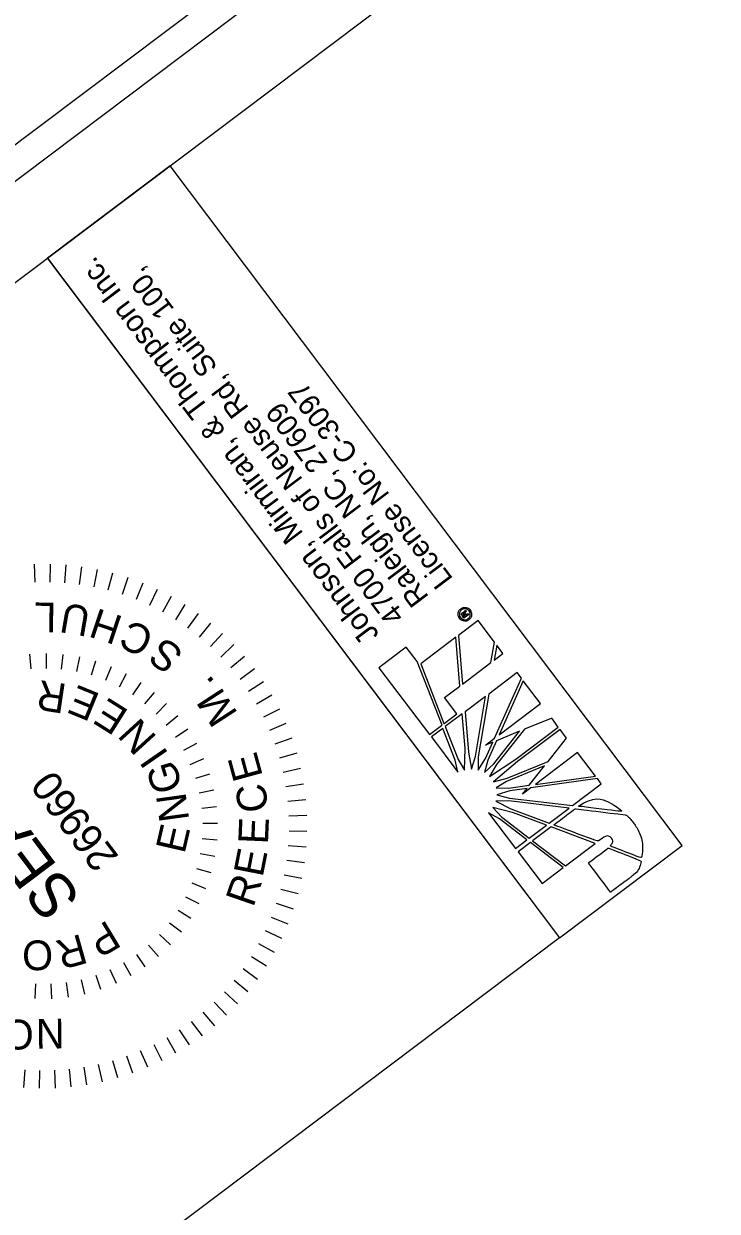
# Model space of a CAD drawing. Extents: x 1262861 to 1264804, y 775326 to 777329.
# Drawn here: x 1263050.9 to 1263158, y 776605.9 to 776789.4 of the extents above; entities that cross this region are included whole.
import ezdxf

# ---------------------------------------------------------------- set-up
doc = ezdxf.new("R2010")
doc.units = 0
for name, color, linetype in [('Default', 7, 'Continuous'), ('Sheet Data Field CELL', 7, 'Continuous'), ('Sheet Plan CELL', 7, 'Continuous'), ('Sheet Plot Border Inside CELL', 7, 'Continuous'), ('Sheet Plot Border Outside CELL', 7, 'Continuous'), ('Sheet Typical CELL', 7, 'Continuous')]:
    doc.layers.add(name, color=color, linetype=linetype)

msp = doc.modelspace()

# ---------------------------------------------------------------- linework, layer by layer
at = {"layer": 'Default'}
for p, q in [((1263052.5, 776705.87), (1263052.61, 776703.11)), ((1263054.94, 776705.89), (1263054.89, 776703.13)), ((1263057.39, 776705.77), (1263057.17, 776703.02)), ((1263059.82, 776705.5), (1263059.43, 776702.77)), ((1263062.23, 776705.08), (1263061.68, 776702.38)), ((1263064.61, 776704.52), (1263063.89, 776701.86)), ((1263066.95, 776703.82), (1263066.08, 776701.2)), ((1263069.25, 776702.98), (1263068.22, 776700.41)), ((1263071.49, 776701.99), (1263070.3, 776699.5)), ((1263073.66, 776700.88), (1263072.33, 776698.46)), ((1263075.77, 776699.64), (1263074.3, 776697.3)), ((1263077.8, 776698.27), (1263076.18, 776696.03)), ((1263079.74, 776696.78), (1263077.99, 776694.64)), ((1263081.59, 776695.18), (1263079.71, 776693.15)), ((1263083.33, 776693.46), (1263081.34, 776691.55)), ((1263051.77, 776691.99), (1263051.98, 776689.7)), ((1263054.35, 776692.1), (1263054.33, 776689.8)), ((1263056.92, 776691.95), (1263056.68, 776689.67)), ((1263059.47, 776691.56), (1263059.01, 776689.3)), ((1263084.97, 776691.65), (1263082.87, 776689.86)), ((1263061.97, 776690.92), (1263061.29, 776688.72)), ((1263064.39, 776690.05), (1263063.51, 776687.92)), ((1263086.5, 776689.74), (1263084.29, 776688.08)), ((1263066.72, 776688.94), (1263065.64, 776686.91)), ((1263068.94, 776687.62), (1263067.66, 776685.7)), ((1263087.91, 776687.74), (1263085.61, 776686.22)), ((1263071.01, 776686.08), (1263069.55, 776684.3)), ((1263089.2, 776685.66), (1263086.81, 776684.28)), ((1263072.93, 776684.36), (1263071.31, 776682.73)), ((1263074.67, 776682.46), (1263072.9, 776680.99)), ((1263090.36, 776683.51), (1263087.89, 776682.28)), ((1263076.22, 776680.4), (1263074.32, 776679.1)), ((1263091.38, 776681.29), (1263088.85, 776680.21)), ((1263092.28, 776679.01), (1263089.67, 776678.08)), ((1263077.56, 776678.2), (1263075.54, 776677.09)), ((1263093.03, 776676.69), (1263090.37, 776675.92)), ((1263076.57, 776674.96), (1263078.69, 776675.86)), ((1263079.58, 776673.46), (1263077.38, 776672.77)), ((1263093.63, 776674.32), (1263090.94, 776673.71)), ((1263080.24, 776670.96), (1263077.98, 776670.49)), ((1263094.1, 776671.92), (1263091.38, 776671.47)), ((1263094.42, 776669.49), (1263091.67, 776669.21)), ((1263080.65, 776668.42), (1263078.36, 776668.16)), ((1263080.82, 776665.85), (1263078.52, 776665.81)), ((1263094.59, 776667.05), (1263091.84, 776666.94)), ((1263094.62, 776664.61), (1263091.86, 776664.66)), ((1263080.74, 776663.27), (1263078.44, 776663.45)), ((1263094.49, 776662.16), (1263091.74, 776662.38)), ((1263080.4, 776660.71), (1263078.14, 776661.12)), ((1263094.22, 776659.73), (1263091.49, 776660.12)), ((1263079.83, 776658.2), (1263077.61, 776658.82)), ((1263079.01, 776655.75), (1263076.87, 776656.59)), ((1263093.81, 776657.32), (1263091.11, 776657.87)), ((1263077.96, 776653.4), (1263075.91, 776654.43)), ((1263093.25, 776654.94), (1263090.58, 776655.65)), ((1263092.54, 776652.6), (1263089.93, 776653.47)), ((1263076.7, 776651.16), (1263074.75, 776652.38)), ((1263091.7, 776650.3), (1263089.14, 776651.33)), ((1263075.22, 776649.04), (1263073.4, 776650.45)), ((1263090.72, 776648.06), (1263088.23, 776649.24)), ((1263073.53, 776647.09), (1263071.86, 776648.66)), ((1263089.6, 776645.89), (1263087.19, 776647.22)), ((1263069.65, 776643.7), (1263068.32, 776645.57)), ((1263071.68, 776645.3), (1263070.17, 776647.03)), ((1263088.36, 776643.78), (1263086.03, 776645.25)), ((1263067.48, 776642.3), (1263066.33, 776644.29)), ((1263060.32, 776639.45), (1263059.79, 776641.69)), ((1263062.8, 776640.17), (1263062.05, 776642.35)), ((1263065.19, 776641.12), (1263064.24, 776643.22)), ((1263085.5, 776639.81), (1263083.37, 776641.56)), ((1263087, 776641.75), (1263084.75, 776643.37)), ((1263052.64, 776638.77), (1263052.77, 776641.06)), ((1263055.22, 776638.75), (1263055.13, 776641.05)), ((1263057.78, 776638.98), (1263057.47, 776641.26)), ((1263083.9, 776637.96), (1263081.87, 776639.83)), ((1263082.19, 776636.22), (1263080.28, 776638.21)), ((1263080.38, 776634.58), (1263078.59, 776636.68)), ((1263078.47, 776633.05), (1263076.81, 776635.25)), ((1263074.39, 776630.35), (1263073.01, 776632.74)), ((1263076.47, 776631.64), (1263074.94, 776633.94)), ((1263070.02, 776628.17), (1263068.93, 776630.7)), ((1263072.24, 776629.19), (1263071, 776631.66)), ((1263065.41, 776626.52), (1263064.64, 776629.18)), ((1263067.74, 776627.27), (1263066.81, 776629.88)), ((1263050.89, 776625.05), (1263051.11, 776627.8)), ((1263053.33, 776624.93), (1263053.38, 776627.69)), ((1263055.77, 776624.96), (1263055.66, 776627.71)), ((1263058.21, 776625.13), (1263057.94, 776627.87)), ((1263060.64, 776625.45), (1263060.2, 776628.17)), ((1263063.04, 776625.92), (1263062.43, 776628.61))]:
    msp.add_line(p, q, dxfattribs=at)
at = {"layer": 'Sheet Data Field CELL'}
for p, q in [((1263119.67, 776698.65), (1263119.66, 776698.66)), ((1263119.67, 776698.65), (1263119.83, 776698.77)), ((1263119.83, 776698.77), (1263119.67, 776698.65)), ((1263119.83, 776698.78), (1263119.83, 776698.77)), ((1263121.05, 776697.18), (1263118, 776694.88)), ((1263118.18, 776697.53), (1263118.34, 776697.65)), ((1263118.34, 776697.65), (1263118.18, 776697.53)), ((1263118.62, 776697.86), (1263118.59, 776697.91)), ((1263118.62, 776697.86), (1263118.77, 776697.97)), ((1263118.77, 776697.97), (1263118.62, 776697.86)), ((1263118.86, 776697.56), (1263118.62, 776697.86)), ((1263118.75, 776697.99), (1263118.77, 776697.97)), ((1263118.77, 776697.97), (1263118.87, 776697.83)), ((1263119.61, 776698.12), (1263118.86, 776697.56)), ((1263118.87, 776697.83), (1263119.05, 776697.97)), ((1263118.95, 776698.1), (1263118.94, 776698.11)), ((1263118.95, 776698.1), (1263119.08, 776698.21)), ((1263119.08, 776698.21), (1263118.95, 776698.1)), ((1263119.05, 776697.97), (1263118.95, 776698.1)), ((1263119.08, 776698.21), (1263119.18, 776698.07)), ((1263119.08, 776698.21), (1263119.08, 776698.21)), ((1263119.18, 776698.07), (1263119.48, 776698.29)), ((1263119.48, 776698.29), (1263119.61, 776698.12)), ((1263123.56, 776693.85), (1263121.05, 776697.18)), ((1263118, 776694.88), (1263118.64, 776687.38)), ((1263109.96, 776693.08), (1263105.74, 776689.88)), ((1263111.62, 776690.88), (1263109.96, 776693.08)), ((1263117.62, 776694.59), (1263112.2, 776690.5)), ((1263118.23, 776687.07), (1263117.62, 776694.59)), ((1263123.03, 776690.69), (1263123.56, 776693.85)), ((1263123.93, 776693.36), (1263123.51, 776691.05)), ((1263124.89, 776692.09), (1263123.93, 776693.36)), ((1263123.51, 776691.05), (1263124.89, 776692.09)), ((1263105.74, 776689.88), (1263113.53, 776679.56)), ((1263115.48, 776681.04), (1263111.62, 776690.88)), ((1263112.2, 776690.5), (1263115.77, 776681.26)), ((1263118.64, 776687.38), (1263123.03, 776690.69)), ((1263127.1, 776689.16), (1263122.69, 776685.83)), ((1263123.6, 776679), (1263127.75, 776688.29)), ((1263128.03, 776687.87), (1263124.3, 776679.53)), ((1263127.75, 776688.29), (1263127.1, 776689.16)), ((1263130.69, 776684.35), (1263128.03, 776687.87)), ((1263115.88, 776685.29), (1263118.23, 776687.07)), ((1263122.69, 776685.83), (1263121.07, 776676.15)), ((1263117.78, 776682.77), (1263115.88, 776685.29)), ((1263122.18, 776685.45), (1263119.04, 776683.08)), ((1263120.66, 776676.19), (1263122.18, 776685.45)), ((1263124.3, 776679.53), (1263130.69, 776684.35)), ((1263115.8, 776681.28), (1263117.78, 776682.77)), ((1263118.6, 776682.75), (1263115.98, 776680.81)), ((1263119.07, 776677.4), (1263118.6, 776682.75)), ((1263119.04, 776683.08), (1263119.54, 776676.83)), ((1263132.41, 776682.08), (1263128.23, 776680.41)), ((1263133.43, 776680.72), (1263132.41, 776682.08)), ((1263113.53, 776679.56), (1263115.42, 776680.99)), ((1263115.6, 776680.53), (1263113.84, 776679.2)), ((1263115.42, 776680.99), (1263115.48, 776681.04)), ((1263117.53, 776675.6), (1263115.6, 776680.53)), ((1263115.77, 776681.26), (1263115.8, 776681.28)), ((1263115.98, 776680.81), (1263117.99, 776675.74)), ((1263123.46, 776675.07), (1263127.46, 776680.09)), ((1263127.46, 776680.09), (1263123.89, 776678.62)), ((1263128.23, 776680.41), (1263123.91, 776674.94)), ((1263126.89, 776675.77), (1263133.43, 776680.72)), ((1263133.7, 776680.37), (1263127.15, 776675.43)), ((1263134.71, 776679.02), (1263133.7, 776680.37)), ((1263113.84, 776679.2), (1263117.92, 776673.74)), ((1263122.17, 776677.92), (1263123.6, 776679)), ((1263122.17, 776675.88), (1263123.33, 776678.4)), ((1263123.33, 776678.4), (1263122.17, 776677.92)), ((1263123.89, 776678.62), (1263122.55, 776675.61)), ((1263131.87, 776675.43), (1263134.71, 776679.02)), ((1263118.94, 776674.07), (1263119.07, 776677.4)), ((1263119.54, 776676.83), (1263120.02, 776674.22)), ((1263136.41, 776676.82), (1263129.89, 776671.85)), ((1263139.17, 776673.16), (1263136.41, 776676.82)), ((1263117.92, 776673.74), (1263117.53, 776675.6)), ((1263117.99, 776675.74), (1263118.94, 776674.07)), ((1263120.02, 776674.22), (1263120.66, 776676.19)), ((1263121.07, 776676.15), (1263121.05, 776674.09)), ((1263121.05, 776674.09), (1263122.17, 776675.88)), ((1263122.55, 776675.61), (1263122.01, 776673.72)), ((1263122.01, 776673.72), (1263123.46, 776675.07)), ((1263122.83, 776673.1), (1263126.89, 776675.77)), ((1263123.91, 776674.94), (1263122.83, 776673.1)), ((1263127.15, 776675.43), (1263123.44, 776672.29)), ((1263131.31, 776674.75), (1263125.45, 776672.32)), ((1263125.52, 776672.81), (1263131.87, 776675.43)), ((1263128.95, 776671.74), (1263131.31, 776674.75)), ((1263123.44, 776672.29), (1263125.52, 776672.81)), ((1263139.46, 776672.78), (1263129.18, 776671.32)), ((1263129.89, 776671.85), (1263139.17, 776673.16)), ((1263140.07, 776671.97), (1263139.46, 776672.78)), ((1263125.45, 776672.32), (1263123.83, 776671.32)), ((1263123.83, 776671.32), (1263125.81, 776671.29)), ((1263125.81, 776671.29), (1263128.95, 776671.74)), ((1263128.6, 776671.25), (1263125.95, 776670.87)), ((1263129.18, 776671.32), (1263127.89, 776670.34)), ((1263127.89, 776670.34), (1263128.6, 776671.25)), ((1263135.62, 776668.6), (1263140.07, 776671.97)), ((1263125.8, 776669.32), (1263123.76, 776669.27)), ((1263123.76, 776669.27), (1263126.12, 776668.11)), ((1263125.95, 776670.87), (1263123.92, 776670.28)), ((1263123.92, 776670.28), (1263125.91, 776669.74)), ((1263135.1, 776668.21), (1263125.8, 776669.32)), ((1263125.91, 776669.74), (1263135.62, 776668.6)), ((1263124.33, 776666.55), (1263122.64, 776667.48)), ((1263122.64, 776667.48), (1263126.81, 776661.96)), ((1263126.49, 776667.5), (1263123.3, 776668.29)), ((1263123.3, 776668.29), (1263124.71, 776666.83)), ((1263126.12, 776668.11), (1263132.04, 776665.9)), ((1263131.61, 776665.58), (1263126.49, 776667.5)), ((1263132.04, 776665.9), (1263135.1, 776668.21)), ((1263128.57, 776663.29), (1263124.33, 776666.55)), ((1263124.71, 776666.83), (1263128.95, 776663.57)), ((1263128.95, 776663.57), (1263131.61, 776665.58)), ((1263132.32, 776665.31), (1263129.47, 776663.17)), ((1263139.13, 776662.75), (1263132.32, 776665.31)), ((1263126.81, 776661.96), (1263128.57, 776663.29)), ((1263129.12, 776662.9), (1263127.22, 776661.47)), ((1263134.18, 776659.02), (1263129.12, 776662.9)), ((1263129.47, 776663.17), (1263134.56, 776659.3)), ((1263134.56, 776659.3), (1263139.13, 776662.75)), ((1263127.22, 776661.47), (1263130.93, 776656.56)), ((1263130.93, 776656.56), (1263134.18, 776659.02))]:
    msp.add_line(p, q, dxfattribs=at)
msp.add_lwpolyline([(1263152.55, 776662.43), (1263073.48, 776767.42), (1263054.53, 776753.15), (1263133.61, 776648.16)], close=True, dxfattribs=at)
for points in [[(1263118.95, 776698.62), (1263118.99, 776698.65), (1263119.01, 776698.68), (1263119.04, 776698.7), (1263119.11, 776698.78), (1263119.23, 776698.63)], [(1263118.64, 776687.38), (1263123.03, 776690.69), (1263123.56, 776693.85), (1263121.05, 776697.18), (1263118, 776694.88), (1263118.64, 776687.38), (1263118.64, 776687.38)], [(1263105.74, 776689.88), (1263113.53, 776679.56), (1263115.42, 776680.99), (1263115.48, 776681.04), (1263111.62, 776690.88), (1263109.96, 776693.08), (1263105.74, 776689.88)], [(1263115.77, 776681.26), (1263115.8, 776681.28), (1263117.78, 776682.77), (1263115.88, 776685.29), (1263118.23, 776687.07), (1263117.62, 776694.59), (1263112.2, 776690.5), (1263115.77, 776681.26)], [(1263124.89, 776692.09), (1263124.89, 776692.09), (1263123.93, 776693.36), (1263123.51, 776691.05), (1263124.89, 776692.09)], [(1263121.05, 776674.09), (1263122.17, 776675.88), (1263123.33, 776678.4), (1263122.17, 776677.92), (1263123.6, 776679), (1263127.75, 776688.29), (1263127.1, 776689.16), (1263122.69, 776685.83), (1263121.07, 776676.15), (1263121.05, 776674.09)], [(1263130.69, 776684.35), (1263128.03, 776687.87), (1263124.3, 776679.53), (1263130.69, 776684.35)], [(1263120.02, 776674.22), (1263120.66, 776676.19), (1263122.18, 776685.45), (1263119.04, 776683.08), (1263119.54, 776676.83), (1263120.02, 776674.22)], [(1263118.94, 776674.07), (1263119.07, 776677.4), (1263118.6, 776682.75), (1263115.98, 776680.81), (1263117.99, 776675.74), (1263118.94, 776674.07)], [(1263122.83, 776673.1), (1263126.89, 776675.77), (1263133.43, 776680.72), (1263132.41, 776682.08), (1263128.23, 776680.41), (1263123.91, 776674.94), (1263122.83, 776673.1)], [(1263117.53, 776675.6), (1263115.6, 776680.53), (1263113.84, 776679.2), (1263117.92, 776673.74), (1263117.53, 776675.6)], [(1263122.01, 776673.72), (1263123.46, 776675.07), (1263127.46, 776680.09), (1263123.89, 776678.62), (1263122.55, 776675.61), (1263122.01, 776673.72)], [(1263125.52, 776672.81), (1263131.87, 776675.43), (1263134.71, 776679.02), (1263133.7, 776680.37), (1263127.15, 776675.43), (1263123.44, 776672.29), (1263125.52, 776672.81)], [(1263139.17, 776673.16), (1263136.41, 776676.82), (1263129.89, 776671.85), (1263139.17, 776673.16)], [(1263123.83, 776671.32), (1263125.81, 776671.29), (1263128.95, 776671.74), (1263131.31, 776674.75), (1263125.45, 776672.32), (1263123.83, 776671.32)], [(1263123.92, 776670.28), (1263125.91, 776669.74), (1263135.62, 776668.6), (1263140.07, 776671.97), (1263139.46, 776672.78), (1263129.18, 776671.32), (1263127.89, 776670.34), (1263128.6, 776671.25), (1263125.95, 776670.87), (1263123.92, 776670.28)], [(1263132.04, 776665.9), (1263135.1, 776668.21), (1263125.8, 776669.32), (1263123.76, 776669.27), (1263126.12, 776668.11), (1263132.04, 776665.9)], [(1263124.33, 776666.55), (1263122.64, 776667.48), (1263126.81, 776661.96), (1263128.57, 776663.29), (1263124.33, 776666.55)], [(1263128.95, 776663.57), (1263131.61, 776665.58), (1263126.49, 776667.5), (1263123.3, 776668.29), (1263124.71, 776666.83), (1263128.95, 776663.57)], [(1263139.13, 776662.75), (1263132.32, 776665.31), (1263129.47, 776663.17), (1263134.56, 776659.3), (1263139.13, 776662.75)], [(1263134.18, 776659.02), (1263129.12, 776662.9), (1263127.22, 776661.47), (1263130.93, 776656.56), (1263134.18, 776659.02)]]:
    msp.add_lwpolyline(points, dxfattribs=at)
for points, degree in [([(1263118.18, 776697.53), (1263118.01, 776697.76), (1263117.94, 776698.02), (1263117.97, 776698.3), (1263118, 776698.58), (1263118.13, 776698.81), (1263118.37, 776698.99)], 3), ([(1263119.66, 776698.66), (1263119.52, 776698.84), (1263119.34, 776698.95), (1263119.12, 776698.98), (1263118.89, 776699.02), (1263118.67, 776698.96), (1263118.49, 776698.82), (1263118.31, 776698.68), (1263118.19, 776698.49), (1263118.16, 776698.26), (1263118.14, 776698.04), (1263118.19, 776697.84), (1263118.34, 776697.65)], 3), ([(1263119.83, 776698.77), (1263120, 776698.55), (1263120.07, 776698.29), (1263120.03, 776698), (1263120, 776697.72), (1263119.86, 776697.49), (1263119.63, 776697.31), (1263119.4, 776697.14), (1263119.14, 776697.07), (1263118.86, 776697.12), (1263118.58, 776697.17), (1263118.36, 776697.3), (1263118.18, 776697.53)], 3), ([(1263118.34, 776697.65), (1263118.48, 776697.46), (1263118.66, 776697.35), (1263118.88, 776697.31), (1263119.11, 776697.28), (1263119.32, 776697.34), (1263119.5, 776697.48), (1263119.69, 776697.62), (1263119.8, 776697.81), (1263119.83, 776698.04), (1263119.86, 776698.26), (1263119.81, 776698.47), (1263119.67, 776698.65)], 3), ([(1263118.37, 776698.99), (1263118.6, 776699.16), (1263118.86, 776699.23), (1263119.14, 776699.19), (1263119.42, 776699.15), (1263119.65, 776699.01), (1263119.83, 776698.78)], 3), ([(1263118.59, 776697.91), (1263118.44, 776698.1), (1263118.45, 776698.25), (1263118.6, 776698.37), (1263118.67, 776698.42), (1263118.74, 776698.43), (1263118.83, 776698.4)], 3), ([(1263118.83, 776698.4), (1263118.82, 776698.47), (1263118.86, 776698.54), (1263118.95, 776698.62)], 2), ([(1263119.23, 776698.63), (1263119.2, 776698.58), (1263119.17, 776698.53), (1263119.12, 776698.49), (1263119.05, 776698.44), (1263119.01, 776698.4), (1263119.01, 776698.36)], 3), ([(1263118.94, 776698.11), (1263118.86, 776698.22), (1263118.78, 776698.25), (1263118.72, 776698.2), (1263118.67, 776698.16), (1263118.68, 776698.09), (1263118.75, 776697.99)], 3), ([(1263119.01, 776698.36), (1263119.01, 776698.33), (1263119.03, 776698.28), (1263119.08, 776698.21)], 2), ([(1263136.55, 776668.5), (1263136.55, 776668.5), (1263143.38, 776667.66), (1263143.38, 776667.66), (1263141.5, 776669.18), (1263138.86, 776670.11), (1263136.55, 776668.5)], 3), ([(1263141.65, 776663.54), (1263141.87, 776663.25), (1263141.9, 776662.88), (1263141.43, 776662.36), (1263141.43, 776662.36), (1263146.27, 776660.48), (1263146.27, 776660.48), (1263146.6, 776662.43), (1263145.97, 776664.68), (1263144.86, 776666.15), (1263144.57, 776666.53), (1263144.32, 776666.79), (1263143.93, 776667.14), (1263143.93, 776667.14), (1263136.03, 776668.11), (1263136.03, 776668.11), (1263136.03, 776668.11), (1263132.72, 776665.62), (1263132.72, 776665.62), (1263132.72, 776665.62), (1263139.55, 776663.06), (1263139.55, 776663.06), (1263140.79, 776664), (1263141.34, 776663.95), (1263141.65, 776663.54)], 3), ([(1263141.65, 776663.54), (1263141.87, 776663.25), (1263141.9, 776662.88), (1263141.43, 776662.36), (1263141.43, 776662.36), (1263146.27, 776660.48), (1263146.27, 776660.48), (1263146.6, 776662.43), (1263145.97, 776664.68), (1263144.86, 776666.15), (1263144.57, 776666.53), (1263144.32, 776666.79), (1263143.93, 776667.14), (1263143.93, 776667.14), (1263136.03, 776668.11), (1263136.03, 776668.11), (1263136.03, 776668.11), (1263132.72, 776665.62), (1263132.72, 776665.62), (1263132.72, 776665.62), (1263139.55, 776663.06), (1263139.55, 776663.06), (1263140.79, 776664), (1263141.34, 776663.95), (1263141.65, 776663.54)], 3), ([(1263138.09, 776659.75), (1263138.09, 776659.75), (1263141.52, 776655.21), (1263141.52, 776655.21), (1263141.52, 776655.21), (1263144.36, 776657.35), (1263144.36, 776657.35), (1263144.36, 776657.35), (1263144.66, 776657.58), (1263144.66, 776657.58), (1263145.55, 776658.25), (1263146.04, 776659.08), (1263146.24, 776660.04), (1263146.24, 776660.04), (1263141.15, 776662.06), (1263141.1, 776662.02), (1263141.1, 776662.02), (1263138.09, 776659.75), (1263138.09, 776659.75)], 3)]:
    msp.add_open_spline(points, degree=degree, dxfattribs=at)
at = {"layer": 'Sheet Plan CELL'}
msp.add_lwpolyline([(1263054.56, 776753.11), (1263133.61, 776648.16), (1263043.77, 776580.5), (1262964.72, 776685.44)], dxfattribs=at)
msp.add_lwpolyline([(1263054.56, 776753.11), (1263133.61, 776648.16), (1263043.77, 776580.5), (1262964.72, 776685.44)], dxfattribs=at)
at = {"layer": 'Sheet Plot Border Inside CELL'}
msp.add_lwpolyline([(1264780.22, 775982.89), (1263777.88, 777313.61), (1262935.19, 776678.9), (1263937.52, 775348.16)], close=True, dxfattribs=at)
at = {"layer": 'Sheet Plot Border Outside CELL'}
msp.add_lwpolyline([(1262916.5, 776670.46), (1263929.36, 775325.74), (1264804.01, 775984.53), (1263791.15, 777329.26)], close=True, dxfattribs=at)
at = {"layer": 'Sheet Typical CELL'}
msp.add_line((1262944.69, 776670.41), (1263783.4, 777302.14), dxfattribs=at)

# ---------------------------------------------------------------- texts
at = {"layer": 'Default'}
for s, height, rotation, p in [('L', 4.6, 179.1415, (1263055.96, 776699.93)), ('U', 4.6, 170.2588, (1263061.41, 776699.21)), ('H', 4.6, 161.3762, (1263066.4, 776697.73)), ('C', 4.6, 152.5536, (1263071.31, 776695.41)), ('S', 4.6, 143.551, (1263075.8, 776692.36)), ('R', 4.6, 171.4993, (1263057.69, 776687.34)), ('.', 4.6, 130.7667, (1263080.54, 776687.69)), ('E', 4.6, 157.7282, (1263062.88, 776685.77)), ('M', 4.6, 123.0244, (1263084.03, 776682.81)), ('E', 4.6, 147.7423, (1263067.28, 776683.18)), ('N', 4.6, 132.3503, (1263071.6, 776679.14)), ('I', 4.6, 124.7206, (1263073.35, 776676.55)), ('E', 4.6, 105.229, (1263087.84, 776673.14)), ('G', 4.6, 106.6258, (1263075.46, 776671.29)), ('SEAL', 6.899, 126.9344, (1263059.91, 776654.29)), ('26960', 4.596, 126.9344, (1263065.67, 776660.7)), ('C', 4.6, 96.2566, (1263088.63, 776667.77)), ('N', 4.6, 97.8596, (1263076.45, 776666.4)), ('E', 4.6, 77.0045, (1263075.7, 776661.02)), ('E', 4.6, 87.584, (1263088.59, 776662.56)), ('E', 4.6, 78.9412, (1263087.77, 776657.41)), ('R', 4.6, 70.8694, (1263086.31, 776652.75)), ('P', 4.6, 211.0638, (1263063.84, 776650.99)), ('O', 4.6, 180.4713, (1263055.39, 776647.79)), ('R', 4.6, 195.7675, (1263059.78, 776648.81)), ('O', 4.6, 178.6517, (1263052.47, 776635.46)), ('N', 4.6, 180.6111, (1263057.16, 776635.68))]:
    msp.add_text(s, height=height, rotation=rotation, dxfattribs=at).set_placement(p)
at = {"layer": 'Sheet Data Field CELL'}
for s, height, p in [('Johnson, Mirmiran, & Thompson Inc.', 3.3582, (1263105.89, 776695.05)), ('4700 Falls of Neuse Rd, Suite 100, ', 3.2623, (1263109.83, 776698.02)), ('License No: C-3097', 3.2623, (1263117.28, 776703.62)), ('Raleigh, NC, 27609', 3.2623, (1263113.55, 776700.82))]:
    msp.add_text(s, height=height, rotation=126.9874, dxfattribs=at).set_placement(p)

doc.saveas('drawing.dxf')
